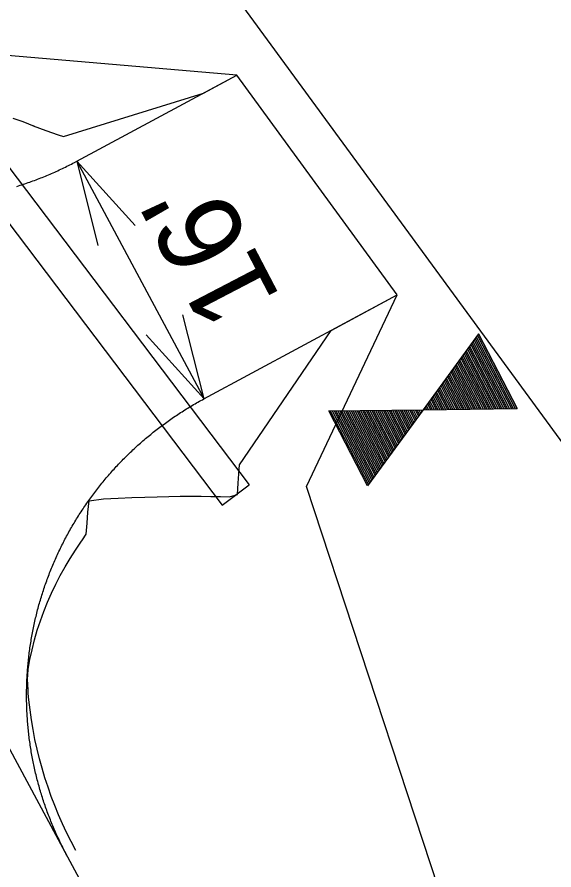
# Model space of a CAD drawing. Extents: x 1627557 to 1636561, y 783843 to 794002.
# Drawn here: x 1627882.9 to 1627914.8, y 785250.8 to 785301.4 of the extents above; entities that cross this region are included whole.
import ezdxf

# ---------------------------------------------------------------- set-up
doc = ezdxf.new("R2010")
doc.units = 0
for name, color, linetype in [('Driveway Dimensions', 7, 'Continuous'), ('GATE', 7, 'Continuous'), ('R_Driveway', 7, 'Continuous'), ('R_Driveway Slope', 7, 'Continuous'), ('R_Proposed Const Limits', 7, 'Continuous'), ('R_Proposed Road', 7, 'Continuous'), ('R_Temp Const Easement', 7, 'Continuous'), ('R_Water', 7, 'Continuous')]:
    doc.layers.add(name, color=color, linetype=linetype)

msp = doc.modelspace()

# ---------------------------------------------------------------- linework, layer by layer
at = {"layer": 'Driveway Dimensions'}
for p, q in [((1627886.469, 785292.878), (1627894.034, 785278.78)), ((1627886.469, 785292.878), (1627889.933, 785289.063)), ((1627886.469, 785292.878), (1627887.732, 785287.883)), ((1627894.034, 785278.78), (1627892.778, 785283.766)), ((1627894.034, 785278.78), (1627890.586, 785282.576))]:
    msp.add_line(p, q, dxfattribs=at)
at = {"layer": 'GATE'}
for p, q in [((1627909.994, 785282.175), (1627912.051, 785278.188)), ((1627910.06, 785282.265), (1627912.163, 785278.189)), ((1627910.126, 785282.355), (1627912.275, 785278.191)), ((1627910.192, 785282.446), (1627912.386, 785278.192)), ((1627910.258, 785282.536), (1627912.498, 785278.194)), ((1627910.324, 785282.626), (1627912.61, 785278.195)), ((1627909.665, 785281.723), (1627911.492, 785278.181)), ((1627909.73, 785281.814), (1627911.604, 785278.182)), ((1627909.796, 785281.904), (1627911.716, 785278.184)), ((1627909.862, 785281.994), (1627911.827, 785278.185)), ((1627909.928, 785282.084), (1627911.939, 785278.187)), ((1627909.269, 785281.182), (1627910.821, 785278.172)), ((1627909.335, 785281.272), (1627910.933, 785278.174)), ((1627909.401, 785281.362), (1627911.045, 785278.175)), ((1627909.467, 785281.452), (1627911.157, 785278.177)), ((1627909.533, 785281.543), (1627911.268, 785278.178)), ((1627909.599, 785281.633), (1627911.38, 785278.179)), ((1627908.873, 785280.64), (1627910.151, 785278.164)), ((1627908.939, 785280.73), (1627910.262, 785278.165)), ((1627909.005, 785280.82), (1627910.374, 785278.167)), ((1627909.071, 785280.911), (1627910.486, 785278.168)), ((1627909.137, 785281.001), (1627910.598, 785278.17)), ((1627909.203, 785281.091), (1627910.71, 785278.171)), ((1627908.543, 785280.188), (1627909.592, 785278.157)), ((1627908.609, 785280.279), (1627909.703, 785278.158)), ((1627908.675, 785280.369), (1627909.815, 785278.16)), ((1627908.741, 785280.459), (1627909.927, 785278.161)), ((1627908.807, 785280.55), (1627910.039, 785278.163)), ((1627908.148, 785279.647), (1627908.921, 785278.148)), ((1627908.214, 785279.737), (1627909.033, 785278.15)), ((1627908.28, 785279.827), (1627909.144, 785278.151)), ((1627908.346, 785279.918), (1627909.256, 785278.153)), ((1627908.412, 785280.008), (1627909.368, 785278.154)), ((1627908.478, 785280.098), (1627909.48, 785278.155)), ((1627907.818, 785279.195), (1627908.362, 785278.141)), ((1627907.884, 785279.286), (1627908.474, 785278.143)), ((1627907.95, 785279.376), (1627908.585, 785278.144)), ((1627908.016, 785279.466), (1627908.697, 785278.146)), ((1627908.082, 785279.556), (1627908.809, 785278.147)), ((1627907.422, 785278.654), (1627907.691, 785278.133)), ((1627907.488, 785278.744), (1627907.803, 785278.134)), ((1627907.554, 785278.834), (1627907.915, 785278.136)), ((1627907.62, 785278.924), (1627908.026, 785278.137)), ((1627907.686, 785279.015), (1627908.138, 785278.138)), ((1627907.752, 785279.105), (1627908.25, 785278.14)), ((1627904.657, 785278.094), (1627905.632, 785276.203)), ((1627904.768, 785278.096), (1627905.698, 785276.293)), ((1627904.88, 785278.097), (1627905.764, 785276.383)), ((1627904.992, 785278.098), (1627905.83, 785276.473)), ((1627905.104, 785278.1), (1627905.896, 785276.564)), ((1627905.215, 785278.101), (1627905.962, 785276.654)), ((1627905.327, 785278.103), (1627906.028, 785276.744)), ((1627905.439, 785278.104), (1627906.094, 785276.835)), ((1627905.551, 785278.106), (1627906.16, 785276.925)), ((1627905.663, 785278.107), (1627906.226, 785277.015)), ((1627905.774, 785278.108), (1627906.292, 785277.105)), ((1627905.886, 785278.11), (1627906.358, 785277.196)), ((1627905.998, 785278.111), (1627906.424, 785277.286)), ((1627906.11, 785278.113), (1627906.49, 785277.376)), ((1627906.222, 785278.114), (1627906.556, 785277.467)), ((1627906.333, 785278.115), (1627906.622, 785277.557)), ((1627906.445, 785278.117), (1627906.688, 785277.647)), ((1627906.557, 785278.118), (1627906.753, 785277.737)), ((1627906.669, 785278.12), (1627906.819, 785277.828)), ((1627906.781, 785278.121), (1627906.885, 785277.918)), ((1627906.892, 785278.123), (1627906.951, 785278.008)), ((1627907.004, 785278.124), (1627907.017, 785278.099)), ((1627907.093, 785278.202), (1627907.132, 785278.126)), ((1627907.159, 785278.292), (1627907.244, 785278.127)), ((1627907.225, 785278.383), (1627907.356, 785278.129)), ((1627907.291, 785278.473), (1627907.467, 785278.13)), ((1627907.356, 785278.563), (1627907.579, 785278.131)), ((1627901.526, 785278.055), (1627903.786, 785273.675)), ((1627901.638, 785278.056), (1627903.852, 785273.765)), ((1627901.75, 785278.057), (1627903.918, 785273.855)), ((1627901.862, 785278.059), (1627903.984, 785273.946)), ((1627901.973, 785278.06), (1627904.05, 785274.036)), ((1627902.085, 785278.062), (1627904.116, 785274.126)), ((1627902.197, 785278.063), (1627904.182, 785274.216)), ((1627902.309, 785278.065), (1627904.248, 785274.307)), ((1627902.421, 785278.066), (1627904.314, 785274.397)), ((1627902.532, 785278.067), (1627904.379, 785274.487)), ((1627902.644, 785278.069), (1627904.445, 785274.578)), ((1627902.756, 785278.07), (1627904.511, 785274.668)), ((1627902.868, 785278.072), (1627904.577, 785274.758)), ((1627902.98, 785278.073), (1627904.643, 785274.848)), ((1627903.091, 785278.074), (1627904.709, 785274.939)), ((1627903.203, 785278.076), (1627904.775, 785275.029)), ((1627903.315, 785278.077), (1627904.841, 785275.119)), ((1627903.427, 785278.079), (1627904.907, 785275.21)), ((1627903.539, 785278.08), (1627904.973, 785275.3)), ((1627903.65, 785278.082), (1627905.039, 785275.39)), ((1627903.762, 785278.083), (1627905.105, 785275.48)), ((1627903.874, 785278.084), (1627905.171, 785275.571)), ((1627903.986, 785278.086), (1627905.237, 785275.661)), ((1627904.098, 785278.087), (1627905.303, 785275.751)), ((1627904.209, 785278.089), (1627905.369, 785275.841)), ((1627904.321, 785278.09), (1627905.435, 785275.932)), ((1627904.433, 785278.091), (1627905.501, 785276.022)), ((1627904.545, 785278.093), (1627905.566, 785276.112))]:
    msp.add_line(p, q, dxfattribs=at)
for points in [[(1627910.333, 785282.639), (1627907.036, 785278.125), (1627912.626, 785278.195)], [(1627901.446, 785278.054), (1627907.036, 785278.125), (1627903.739, 785273.61)]]:
    msp.add_lwpolyline(points, close=True, dxfattribs=at)
at = {"layer": 'R_Driveway'}
for points in [[(1627882.92, 785291.389), (1627883.015, 785291.419), (1627883.111, 785291.45), (1627883.206, 785291.48), (1627883.301, 785291.512), (1627883.396, 785291.544), (1627883.49, 785291.576), (1627883.585, 785291.609), (1627883.679, 785291.642), (1627883.773, 785291.675), (1627883.867, 785291.71), (1627883.961, 785291.744), (1627884.055, 785291.779), (1627884.148, 785291.815), (1627884.241, 785291.851), (1627884.335, 785291.887), (1627884.427, 785291.924), (1627884.52, 785291.962), (1627884.613, 785291.999), (1627884.705, 785292.038), (1627884.797, 785292.077), (1627884.889, 785292.116), (1627884.981, 785292.156), (1627885.073, 785292.196), (1627885.164, 785292.236), (1627885.255, 785292.277), (1627885.346, 785292.319), (1627885.437, 785292.361), (1627885.527, 785292.403), (1627885.618, 785292.446), (1627885.708, 785292.49), (1627885.798, 785292.533), (1627885.887, 785292.578), (1627885.977, 785292.622), (1627886.066, 785292.668), (1627886.155, 785292.713), (1627886.244, 785292.759), (1627886.332, 785292.806), (1627886.469, 785292.878), (1627895.98, 785297.995)], [(1627885.882, 785251.681), (1627885.826, 785251.785), (1627885.78, 785251.873), (1627885.733, 785251.962), (1627885.688, 785252.051), (1627885.642, 785252.14), (1627885.598, 785252.229), (1627885.553, 785252.319), (1627885.509, 785252.409), (1627885.466, 785252.499), (1627885.423, 785252.589), (1627885.38, 785252.679), (1627885.338, 785252.77), (1627885.296, 785252.861), (1627885.255, 785252.952), (1627885.214, 785253.043), (1627885.174, 785253.135), (1627885.134, 785253.226), (1627885.094, 785253.318), (1627885.055, 785253.41), (1627885.017, 785253.503), (1627884.979, 785253.595), (1627884.941, 785253.688), (1627884.904, 785253.781), (1627884.867, 785253.874), (1627884.831, 785253.967), (1627884.796, 785254.06), (1627884.76, 785254.154), (1627884.725, 785254.248), (1627884.691, 785254.342), (1627884.657, 785254.436), (1627884.624, 785254.53), (1627884.591, 785254.624), (1627884.559, 785254.719), (1627884.527, 785254.814), (1627884.495, 785254.909), (1627884.464, 785255.004), (1627884.434, 785255.099), (1627884.404, 785255.194), (1627884.374, 785255.29), (1627884.345, 785255.386), (1627884.316, 785255.481), (1627884.288, 785255.577), (1627884.26, 785255.673), (1627884.233, 785255.77), (1627884.207, 785255.866), (1627884.18, 785255.963), (1627884.155, 785256.059), (1627884.129, 785256.156), (1627884.105, 785256.253), (1627884.08, 785256.35), (1627884.056, 785256.447), (1627884.033, 785256.544), (1627884.01, 785256.642), (1627883.988, 785256.739), (1627883.966, 785256.837), (1627883.945, 785256.934), (1627883.924, 785257.032), (1627883.904, 785257.13), (1627883.884, 785257.228), (1627883.864, 785257.326), (1627883.845, 785257.424), (1627883.827, 785257.523), (1627883.809, 785257.621), (1627883.791, 785257.719), (1627883.775, 785257.818), (1627883.758, 785257.917), (1627883.742, 785258.015), (1627883.727, 785258.114), (1627883.712, 785258.213), (1627883.697, 785258.312), (1627883.683, 785258.411), (1627883.67, 785258.51), (1627883.657, 785258.609), (1627883.644, 785258.708), (1627883.632, 785258.808), (1627883.621, 785258.907), (1627883.61, 785259.006), (1627883.599, 785259.106), (1627883.589, 785259.205), (1627883.58, 785259.305), (1627883.571, 785259.405), (1627883.562, 785259.504), (1627883.554, 785259.604), (1627883.547, 785259.704), (1627883.54, 785259.803), (1627883.533, 785259.903), (1627883.527, 785260.003), (1627883.521, 785260.103), (1627883.516, 785260.203), (1627883.512, 785260.303), (1627883.508, 785260.402), (1627883.504, 785260.502), (1627883.501, 785260.602), (1627883.499, 785260.702), (1627883.497, 785260.802), (1627883.495, 785260.902), (1627883.494, 785261.002), (1627883.494, 785261.102), (1627883.494, 785261.202), (1627883.494, 785261.302), (1627883.495, 785261.402), (1627883.497, 785261.502), (1627883.499, 785261.602), (1627883.501, 785261.702), (1627883.504, 785261.802), (1627883.507, 785261.902), (1627883.511, 785262.002), (1627883.516, 785262.102), (1627883.521, 785262.202), (1627883.526, 785262.302), (1627883.532, 785262.401), (1627883.539, 785262.501), (1627883.546, 785262.601), (1627883.553, 785262.701), (1627883.561, 785262.8), (1627883.57, 785262.9), (1627883.579, 785263), (1627883.588, 785263.099), (1627883.598, 785263.199), (1627883.608, 785263.298), (1627883.619, 785263.398), (1627883.631, 785263.497), (1627883.643, 785263.596), (1627883.655, 785263.695), (1627883.668, 785263.795), (1627883.682, 785263.894), (1627883.695, 785263.993), (1627883.71, 785264.092), (1627883.725, 785264.191), (1627883.74, 785264.289), (1627883.756, 785264.388), (1627883.773, 785264.487), (1627883.789, 785264.585), (1627883.807, 785264.684), (1627883.825, 785264.782), (1627883.843, 785264.88), (1627883.862, 785264.979), (1627883.881, 785265.077), (1627883.901, 785265.175), (1627883.921, 785265.273), (1627883.942, 785265.371), (1627883.964, 785265.468), (1627883.985, 785265.566), (1627884.008, 785265.663), (1627884.03, 785265.761), (1627884.054, 785265.858), (1627884.077, 785265.955), (1627884.102, 785266.052), (1627884.126, 785266.149), (1627884.151, 785266.246), (1627884.177, 785266.342), (1627884.203, 785266.439), (1627884.23, 785266.535), (1627884.257, 785266.632), (1627884.285, 785266.728), (1627884.313, 785266.824), (1627884.341, 785266.919), (1627884.37, 785267.015), (1627884.4, 785267.111), (1627884.43, 785267.206), (1627884.46, 785267.301), (1627884.491, 785267.396), (1627884.523, 785267.491), (1627884.555, 785267.586), (1627884.587, 785267.681), (1627884.62, 785267.775), (1627884.653, 785267.87), (1627884.687, 785267.964), (1627884.721, 785268.058), (1627884.756, 785268.151), (1627884.791, 785268.245), (1627884.827, 785268.338), (1627884.863, 785268.432), (1627884.9, 785268.525), (1627884.937, 785268.618), (1627884.974, 785268.71), (1627885.012, 785268.803), (1627885.051, 785268.895), (1627885.09, 785268.987), (1627885.129, 785269.079), (1627885.169, 785269.171), (1627885.209, 785269.262), (1627885.25, 785269.354), (1627885.291, 785269.445), (1627885.333, 785269.536), (1627885.375, 785269.626), (1627885.417, 785269.717), (1627885.46, 785269.807), (1627885.504, 785269.897), (1627885.548, 785269.987), (1627885.592, 785270.077), (1627885.637, 785270.166), (1627885.682, 785270.255), (1627885.728, 785270.344), (1627885.774, 785270.433), (1627885.821, 785270.521), (1627885.868, 785270.61), (1627885.915, 785270.698), (1627885.963, 785270.785), (1627886.011, 785270.873), (1627886.06, 785270.96), (1627886.109, 785271.047), (1627886.159, 785271.134), (1627886.209, 785271.221), (1627886.26, 785271.307), (1627886.311, 785271.393), (1627886.362, 785271.479), (1627886.414, 785271.564), (1627886.466, 785271.65), (1627886.519, 785271.735), (1627886.572, 785271.819), (1627886.625, 785271.904), (1627886.679, 785271.988), (1627886.734, 785272.072), (1627886.788, 785272.156), (1627886.844, 785272.239), (1627886.899, 785272.322), (1627886.955, 785272.405), (1627887.012, 785272.487), (1627887.069, 785272.57), (1627887.126, 785272.652), (1627887.184, 785272.733), (1627887.242, 785272.815), (1627887.3, 785272.896), (1627887.359, 785272.977), (1627887.418, 785273.057), (1627887.478, 785273.137), (1627887.538, 785273.217), (1627887.599, 785273.297), (1627887.659, 785273.376), (1627887.721, 785273.455), (1627887.782, 785273.534), (1627887.844, 785273.612), (1627887.907, 785273.691), (1627887.97, 785273.768), (1627888.033, 785273.846), (1627888.097, 785273.923), (1627888.161, 785274), (1627888.225, 785274.076), (1627888.29, 785274.152), (1627888.355, 785274.228), (1627888.421, 785274.304), (1627888.487, 785274.379), (1627888.553, 785274.454), (1627888.619, 785274.528), (1627888.686, 785274.603), (1627888.754, 785274.677), (1627888.822, 785274.75), (1627888.89, 785274.823), (1627888.958, 785274.896), (1627889.027, 785274.969), (1627889.096, 785275.041), (1627889.166, 785275.113), (1627889.236, 785275.184), (1627889.306, 785275.255), (1627889.377, 785275.326), (1627889.448, 785275.396), (1627889.519, 785275.466), (1627889.591, 785275.536), (1627889.663, 785275.605), (1627889.735, 785275.674), (1627889.808, 785275.743), (1627889.881, 785275.811), (1627889.955, 785275.879), (1627890.029, 785275.947), (1627890.103, 785276.014), (1627890.177, 785276.081), (1627890.252, 785276.147), (1627890.327, 785276.213), (1627890.402, 785276.279), (1627890.478, 785276.344), (1627890.554, 785276.409), (1627890.631, 785276.473), (1627890.707, 785276.537), (1627890.784, 785276.601), (1627890.862, 785276.664), (1627890.94, 785276.727), (1627891.018, 785276.79), (1627891.096, 785276.852), (1627891.174, 785276.914), (1627891.253, 785276.975), (1627891.333, 785277.036), (1627891.412, 785277.097), (1627891.492, 785277.157), (1627891.572, 785277.217), (1627891.653, 785277.276), (1627891.733, 785277.335), (1627891.814, 785277.394), (1627891.896, 785277.452), (1627891.977, 785277.51), (1627892.059, 785277.567), (1627892.141, 785277.624), (1627892.224, 785277.681), (1627892.307, 785277.737), (1627892.39, 785277.793), (1627892.473, 785277.848), (1627892.557, 785277.903), (1627892.64, 785277.957), (1627892.725, 785278.011), (1627892.809, 785278.065), (1627892.894, 785278.118), (1627892.979, 785278.171), (1627893.064, 785278.223), (1627893.149, 785278.275), (1627893.235, 785278.327), (1627893.321, 785278.378), (1627893.407, 785278.429), (1627893.494, 785278.479), (1627893.58, 785278.529), (1627893.667, 785278.578), (1627893.755, 785278.627), (1627893.842, 785278.675), (1627893.93, 785278.723), (1627894.018, 785278.771), (1627905.504, 785284.951)]]:
    msp.add_lwpolyline(points, dxfattribs=at)
at = {"layer": 'R_Driveway Slope'}
for points in [[(1627882.674, 785295.439), (1627883.28, 785295.233), (1627883.939, 785294.972), (1627883.884, 785294.987), (1627884.632, 785294.713), (1627885.37, 785294.452), (1627885.684, 785294.347), (1627893.995, 785296.928), (1627895.98, 785297.995)], [(1627886.421, 785251.96), (1627886.134, 785252.497), (1627885.873, 785253.017), (1627885.625, 785253.544), (1627885.39, 785254.078), (1627885.168, 785254.618), (1627884.96, 785255.164), (1627884.766, 785255.716), (1627884.584, 785256.274), (1627884.416, 785256.836), (1627884.26, 785257.403), (1627884.119, 785257.976), (1627883.992, 785258.553), (1627883.879, 785259.135), (1627883.781, 785259.721), (1627883.699, 785260.311), (1627883.631, 785260.904), (1627883.597, 785261.285), (1627883.578, 785261.501), (1627883.541, 785262.101), (1627883.581, 785262.699), (1627883.689, 785263.29), (1627883.816, 785263.875), (1627883.962, 785264.455), (1627884.127, 785265.028), (1627884.311, 785265.593), (1627884.514, 785266.15), (1627884.735, 785266.699), (1627884.974, 785267.238), (1627885.227, 785267.768), (1627885.497, 785268.288), (1627885.781, 785268.798), (1627886.08, 785269.297), (1627886.393, 785269.785), (1627886.72, 785270.261), (1627886.821, 785270.398), (1627887.036, 785270.739), (1627887.081, 785271.384), (1627887.138, 785272.043), (1627887.207, 785272.717), (1627888.055, 785272.826), (1627888.926, 785272.871), (1627889.748, 785272.906), (1627890.519, 785272.939), (1627891.251, 785272.963), (1627891.948, 785272.979), (1627892.613, 785272.989), (1627893.248, 785272.992), (1627893.856, 785272.989), (1627894.438, 785272.982), (1627894.998, 785272.969), (1627895.536, 785272.952), (1627896.017, 785273.097), (1627896.051, 785273.757), (1627896.115, 785274.599), (1627896.135, 785274.86), (1627901.576, 785282.838), (1627905.504, 785284.951)]]:
    msp.add_lwpolyline(points, dxfattribs=at)
at = {"layer": 'R_Proposed Const Limits'}
msp.add_lwpolyline([(1627932.755, 785211.085), (1627927.025, 785219.351), (1627925.863, 785221.024), (1627925.764, 785221.168), (1627921.681, 785227.075), (1627921.303, 785227.62), (1627918.01, 785232.37), (1627917.976, 785232.419), (1627915.581, 785235.89), (1627910.147, 785243.632), (1627910.139, 785243.643), (1627910.106, 785243.687), (1627909.781, 785244.118), (1627900.106, 785273.564), (1627905.504, 785284.951), (1627895.98, 785297.995), (1627859.504, 785301.128)], dxfattribs=at)
at = {"layer": 'R_Proposed Road'}
msp.add_lwpolyline([(1627894.588, 785235.481), (1627885.246, 785252.852), (1627875.615, 785270.749), (1627866.003, 785288.638), (1627862.813, 785294.595), (1627853.242, 785312.467), (1627838.976, 785339.15), (1627823.773, 785368.507), (1627823.345, 785369.332)], dxfattribs=at)
at = {"layer": 'R_Temp Const Easement'}
msp.add_line((1627930.495, 785255.412), (1627885.813, 785316.473), dxfattribs=at)
at = {"layer": 'R_Water'}
for p, q in [((1627878.436, 785297.805), (1627896.713, 785273.672)), ((1627876.838, 785296.594), (1627895.114, 785272.462)), ((1627895.11, 785272.459), (1627896.709, 785273.669))]:
    msp.add_line(p, q, dxfattribs=at)

# ---------------------------------------------------------------- texts
at = {"layer": 'Driveway Dimensions'}
msp.add_text("16'", height=5, rotation=117.5341, dxfattribs=at).set_placement((1627898.615, 785284.73))

doc.saveas('drawing.dxf')
